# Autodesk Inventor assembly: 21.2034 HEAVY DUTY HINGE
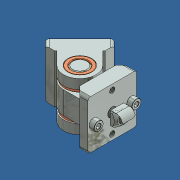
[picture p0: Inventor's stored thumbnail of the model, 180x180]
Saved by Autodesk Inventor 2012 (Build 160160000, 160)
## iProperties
Created: 2014-05
Part Number: 21.2034 HEAVY DUTY HINGE
Document SubType Name: Assembly
Designer: Admin
Author: Admin
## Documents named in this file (9)
- C:\Andys Backup Data\ANDY'S INVENTOR\INVENTOR LIBRARIES\PARTS LIBRARY\LINKS AND HINGES\21.2034 HEAVY DUTY HINGE.iam
- C:\Andys Backup Data\ANDY'S INVENTOR\INVENTOR LIBRARIES\PARTS LIBRARY\LINKS AND HINGES\SUBCOMPONENTS\21.2034 HD HINGE INNER BRACKET.ipt
- C:\Andys Backup Data\ANDY'S INVENTOR\INVENTOR LIBRARIES\PARTS LIBRARY\LINKS AND HINGES\SUBCOMPONENTS\21.2034 HD HINGE OUTER BRACKET.ipt
- C:\Andys Backup Data\ANDY'S INVENTOR\INVENTOR LIBRARIES\PARTS LIBRARY\LINKS AND HINGES\SUBCOMPONENTS\21.2034 HD HINGE PIN.ipt
- C:\Andys Backup Data\ANDY'S INVENTOR\INVENTOR LIBRARIES\PARTS LIBRARY\LINKS AND HINGES\SUBCOMPONENTS\21.2034 HD HINGE BRONZE BUSHING.ipt
- C:\Andys Backup Data\ANDY'S INVENTOR\INVENTOR LIBRARIES\PARTS LIBRARY\FASTENING ELEMENTS\SCREWS CAP\21.1202 M8X20.ipt
- C:\Andys Backup Data\ANDY'S INVENTOR\INVENTOR LIBRARIES\PARTS LIBRARY\FASTENING ELEMENTS\NUTS\21.1351_2 M8 SQUARE NUT POS FXG.ipt
- C:\Andys Backup Data\ANDY'S INVENTOR\INVENTOR LIBRARIES\PARTS LIBRARY\FASTENING ELEMENTS\SCREWS CAP\21.1212 M8X50.ipt
- C:\Andys Backup Data\ANDY'S INVENTOR\INVENTOR LIBRARIES\PARTS LIBRARY\FASTENING ELEMENTS\SCREWS CAP\SHCS M5X6 HIGH HEAD.ipt
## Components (13 placed, 8 different names)
1. 21.2034 HD HINGE INNER BRACKET:1 — Mate:1, Mate:2, Insert:4, Insert:5, Angle:2, Insert:8, Insert:9
2. 21.2034 HD HINGE OUTER BRACKET:1 — Mate:3, Insert:1, Insert:2, Flush:1, Insert:3, Mate:5, Angle:1, Insert:6, Insert:7
3. 21.2034 HD HINGE PIN:1 — Mate:1, Mate:2, Mate:3, Flush:1
4. 21.2034 HD HINGE BRONZE BUSHING:1 — Insert:2
5. 21.2034 HD HINGE BRONZE BUSHING:2 — Insert:1
6. 21.1202  M8 x 20:1 — Insert:3, Mate:4
7. 21.1351_2 M8 SQUARE NUT POS FXG:1 — Mate:4, Mate:5, Angle:1
8. 21.1212 M8 x 50:1 — Insert:4
9. 21.1351_2 M8 SQUARE NUT POS FXG:2 — Insert:5, Angle:2
10. SHCS M5X6 HIGH HEAD:1 — Insert:6
11. SHCS M5X6 HIGH HEAD:2 — Insert:9
12. SHCS M5X6 HIGH HEAD:3 — Insert:7
13. SHCS M5X6 HIGH HEAD:4 — Insert:8
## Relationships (17: Insert 9, Mate 5, Angle 2, Flush 1)
- Mate:1: 21.2034 HD HINGE INNER BRACKET:1 ↔ 21.2034 HD HINGE PIN:1
- Mate:2: 21.2034 HD HINGE INNER BRACKET:1 ↔ 21.2034 HD HINGE PIN:1
- Mate:3: 21.2034 HD HINGE OUTER BRACKET:1 ↔ 21.2034 HD HINGE PIN:1
- Insert:1: 21.2034 HD HINGE OUTER BRACKET:1 ↔ 21.2034 HD HINGE BRONZE BUSHING:2
- Insert:2: 21.2034 HD HINGE OUTER BRACKET:1 ↔ 21.2034 HD HINGE BRONZE BUSHING:1
- Flush:1: 21.2034 HD HINGE OUTER BRACKET:1 ↔ 21.2034 HD HINGE PIN:1
- Insert:3: 21.2034 HD HINGE OUTER BRACKET:1 ↔ 21.1202  M8 x 20:1
- Mate:4: 21.1202  M8 x 20:1 ↔ 21.1351_2 M8 SQUARE NUT POS FXG:1
- Mate:5: 21.2034 HD HINGE OUTER BRACKET:1 ↔ 21.1351_2 M8 SQUARE NUT POS FXG:1
- Insert:4: 21.2034 HD HINGE INNER BRACKET:1 ↔ 21.1212 M8 x 50:1
- Insert:5: 21.2034 HD HINGE INNER BRACKET:1 ↔ 21.1351_2 M8 SQUARE NUT POS FXG:2
- Angle:1: 21.2034 HD HINGE OUTER BRACKET:1 ↔ 21.1351_2 M8 SQUARE NUT POS FXG:1
- Angle:2: 21.2034 HD HINGE INNER BRACKET:1 ↔ 21.1351_2 M8 SQUARE NUT POS FXG:2
- Insert:6: 21.2034 HD HINGE OUTER BRACKET:1 ↔ SHCS M5X6 HIGH HEAD:1
- Insert:7: 21.2034 HD HINGE OUTER BRACKET:1 ↔ SHCS M5X6 HIGH HEAD:3
- Insert:8: 21.2034 HD HINGE INNER BRACKET:1 ↔ SHCS M5X6 HIGH HEAD:4
- Insert:9: 21.2034 HD HINGE INNER BRACKET:1 ↔ SHCS M5X6 HIGH HEAD:2
